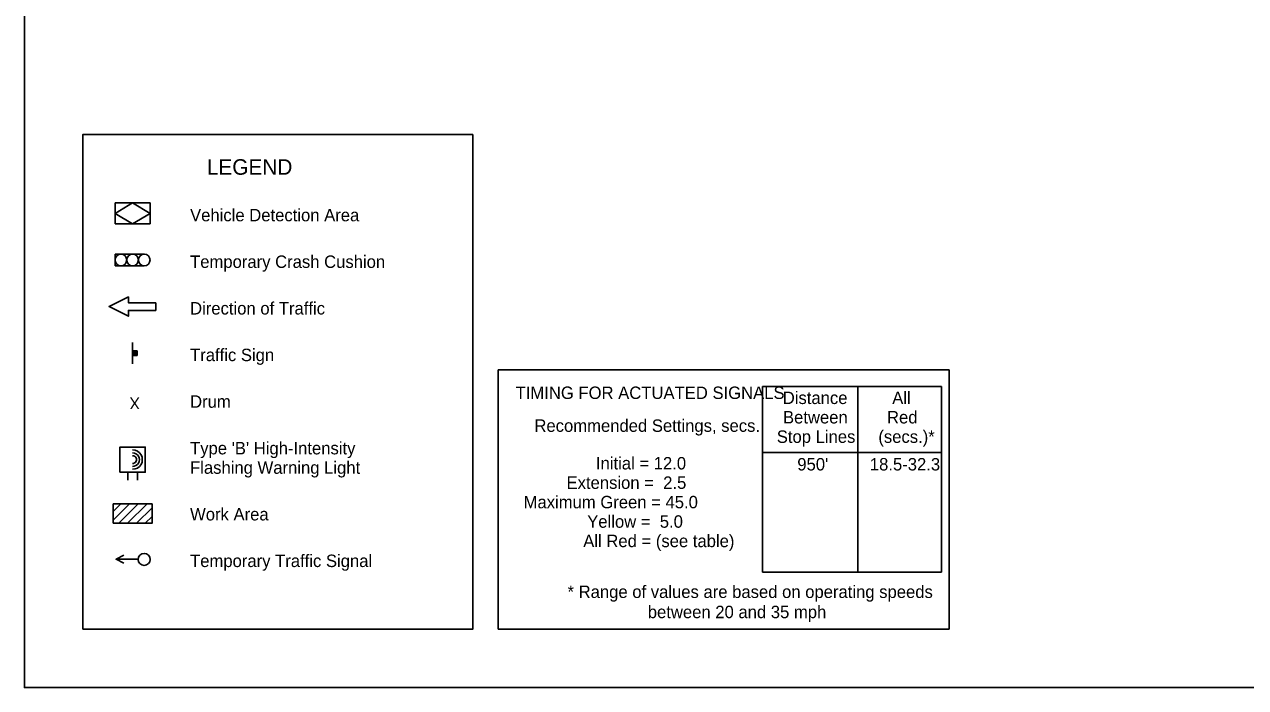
# Model space of a CAD drawing. Extents: x -2134934 to -2122394, y -2140205 to -2137036.
# Drawn here: x -2130232 to -2128661, y -2139046 to -2138192 of the extents above; entities that cross this region are included whole.
import ezdxf

# ---------------------------------------------------------------- set-up
doc = ezdxf.new("R2010")
doc.units = 0
for name, color, linetype in [('BridgeSuperStructureExisting', 7, 'Continuous'), ('Default', 7, 'Continuous'), ('dsnStdLabel', 7, 'Continuous'), ('dsnTextFinalPlan', 7, 'Continuous')]:
    doc.layers.add(name, color=color, linetype=linetype)

msp = doc.modelspace()

# ---------------------------------------------------------------- linework, layer by layer
at = {"layer": 'BridgeSuperStructureExisting'}
for p, q in [((-2130115.3, -2138449.1), (-2130115.3, -2138422.1)), ((-2130115.3, -2138422.1), (-2130070.3, -2138422.1)), ((-2130070.3, -2138449.1), (-2130070.3, -2138422.1)), ((-2130115.3, -2138449.1), (-2130070.3, -2138449.1)), ((-2130115.3, -2138488.1), (-2130115.3, -2138503.1)), ((-2130077.8, -2138488.1), (-2130115.3, -2138488.1)), ((-2130115.3, -2138503.1), (-2130077.8, -2138503.1)), ((-2130092.8, -2138601.9), (-2130092.8, -2138629.4)), ((-2130092.4, -2138618.4), (-2130092.4, -2138612.8)), ((-2130092.1, -2138612.8), (-2130092.1, -2138618.4)), ((-2130091.9, -2138618.4), (-2130091.9, -2138612.8)), ((-2130091.6, -2138612.8), (-2130091.6, -2138618.4)), ((-2130091.4, -2138618.4), (-2130091.4, -2138612.8)), ((-2130091.2, -2138612.8), (-2130091.2, -2138618.4)), ((-2130090.8, -2138618.4), (-2130090.8, -2138612.8)), ((-2130090.6, -2138612.8), (-2130090.6, -2138618.4)), ((-2130090.3, -2138618.4), (-2130090.4, -2138612.8)), ((-2130090, -2138612.8), (-2130090, -2138618.4)), ((-2130089.6, -2138618.4), (-2130089.6, -2138612.8)), ((-2130089.2, -2138612.8), (-2130089.2, -2138618.4)), ((-2130089, -2138618.4), (-2130089, -2138612.8)), ((-2130088.6, -2138612.8), (-2130088.6, -2138618.4)), ((-2130088.3, -2138618.4), (-2130088.3, -2138612.8)), ((-2130088, -2138612.8), (-2130088, -2138618.4)), ((-2130087.8, -2138618.4), (-2130087.8, -2138612.8)), ((-2130087.5, -2138612.8), (-2130087.5, -2138618.4)), ((-2129622.5, -2138636.9), (-2129622.5, -2138970.9)), ((-2129622.5, -2138636.9), (-2129042.5, -2138636.9)), ((-2129042.5, -2138636.9), (-2129042.5, -2138970.9)), ((-2130099.1, -2138768.8), (-2130099.1, -2138778.8)), ((-2130086.6, -2138768.8), (-2130086.6, -2138778.8)), ((-2130117.8, -2138830.5), (-2130096.8, -2138809.5)), ((-2130117.8, -2138819.2), (-2130108.1, -2138809.5)), ((-2130110.5, -2138834.5), (-2130085.5, -2138809.5)), ((-2130099.2, -2138834.5), (-2130074.2, -2138809.5)), ((-2130087.9, -2138834.5), (-2130067.8, -2138814.5)), ((-2130076.6, -2138834.5), (-2130067.8, -2138825.8)), ((-2130085.7, -2138880.6), (-2130113.6, -2138880.6)), ((-2129622.5, -2138970.9), (-2129042.5, -2138970.9))]:
    msp.add_line(p, q, dxfattribs=at)
for points in [[(-2130157, -2138970.9), (-2129655.4, -2138970.9), (-2129655.4, -2138334.3), (-2130157, -2138334.3)], [(-2130063.1, -2138550.6), (-2130063.1, -2138560.6), (-2130098.1, -2138560.6), (-2130098.1, -2138568.1), (-2130123.1, -2138555.6), (-2130098.1, -2138543.1), (-2130098.1, -2138550.6)], [(-2130092.7, -2138618.4), (-2130092.7, -2138612.7), (-2130087.1, -2138612.7), (-2130087.1, -2138618.4)], [(-2130109.1, -2138768.8), (-2130109.1, -2138736.3), (-2130076.6, -2138736.3), (-2130076.6, -2138768.8)], [(-2130117.8, -2138834.5), (-2130067.8, -2138834.5), (-2130067.8, -2138809.5), (-2130117.8, -2138809.5)]]:
    msp.add_lwpolyline(points, close=True, dxfattribs=at)
msp.add_lwpolyline([(-2130104, -2138875.7), (-2130114, -2138880.7), (-2130104, -2138885.7)], dxfattribs=at)
for centre, radius in [((-2130107.8, -2138495.6), 7.5), ((-2130107.8, -2138495.6), 7.5), ((-2130092.8, -2138495.6), 7.5), ((-2130092.8, -2138495.6), 7.5), ((-2130077.8, -2138495.6), 7.5), ((-2130077.8, -2138495.6), 7.5), ((-2130077.9, -2138880.9), 7.74)]:
    msp.add_circle(centre, radius, dxfattribs=at)
for radius in [12.5, 12.5, 8.75, 5]:
    msp.add_arc((-2130092.8, -2138752.5), radius, 269.4041, 90.5445, dxfattribs=at)
at = {"layer": 'Default'}
msp.add_lwpolyline([(-2130232, -2137035.9), (-2127097, -2137035.9), (-2127097, -2139045.9), (-2130232, -2139045.9)], close=True, dxfattribs=at)
at = {"layer": 'dsnStdLabel'}
for p, q in [((-2129282.5, -2138658.5), (-2129282.5, -2138897.6)), ((-2129282.5, -2138658.5), (-2129052.5, -2138658.5)), ((-2129160.2, -2138658.5), (-2129160.2, -2138897.6)), ((-2129052.5, -2138658.5), (-2129052.5, -2138897.6)), ((-2129282.5, -2138743.5), (-2129052.5, -2138743.5)), ((-2129282.5, -2138897.6), (-2129052.5, -2138897.6))]:
    msp.add_line(p, q, dxfattribs=at)
at = {"layer": 'dsnTextFinalPlan'}
msp.add_lwpolyline([(-2130115.3, -2138435.6), (-2130092.8, -2138422.1), (-2130070.3, -2138435.6), (-2130092.8, -2138449.1)], close=True, dxfattribs=at)

# ---------------------------------------------------------------- texts
at = {"layer": 'BridgeSuperStructureExisting'}
msp.add_text('X', height=15, rotation=180, dxfattribs=at).set_placement((-2130083.4, -2138672.2))
at = {"layer": 'dsnStdLabel'}
for s, height, p in [('LEGEND', 20, (-2129997.3, -2138385.9)), ('Vehicle Detection Area', 16, (-2130018.9, -2138445.8)), ('Temporary Crash Cushion', 16, (-2130018.9, -2138505.8)), ('Direction of Traffic', 16, (-2130018.9, -2138565.8)), ('Traffic Sign', 16, (-2130018.9, -2138625.8)), ('TIMING FOR ACTUATED SIGNALS', 16, (-2129600.2, -2138674.5)), ('Distance', 16, (-2129256.6, -2138681)), ('All', 16, (-2129115.8, -2138681)), ('Drum', 16, (-2130018.9, -2138685.8)), ('Between', 16, (-2129256.3, -2138706)), ('Red', 16, (-2129122.5, -2138706)), ('Recommended Settings, secs.', 16, (-2129576, -2138716.8)), ("Type 'B' High-Intensity", 16, (-2130018.9, -2138745.8)), ('Stop Lines', 16, (-2129264.3, -2138731)), (' (secs.)*', 16, (-2129139.6, -2138731)), ('Flashing Warning Light', 16, (-2130018.9, -2138770.8)), ('Initial = 12.0', 16, (-2129496.9, -2138765.2)), ("950'", 16, (-2129237.9, -2138766.5)), ('18.5-32.3', 16, (-2129144.6, -2138766.5)), ('Extension =  2.5', 16, (-2129534.7, -2138790.2)), ('Maximum Green = 45.0', 16, (-2129589.9, -2138815.2)), ('Work Area', 16, (-2130018.9, -2138830.8)), ('Yellow =  5.0', 16, (-2129508.1, -2138840.2)), ('All Red = (see table)', 16, (-2129513.2, -2138865.2)), ('Temporary Traffic Signal', 16, (-2130018.9, -2138890.8)), ('* Range of values are based on operating speeds', 16, (-2129533.4, -2138930.6)), ('between 20 and 35 mph', 16, (-2129430.2, -2138956.6))]:
    msp.add_text(s, height=height, dxfattribs=at).set_placement(p)

doc.saveas('drawing.dxf')
